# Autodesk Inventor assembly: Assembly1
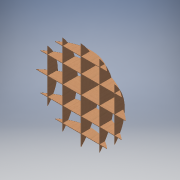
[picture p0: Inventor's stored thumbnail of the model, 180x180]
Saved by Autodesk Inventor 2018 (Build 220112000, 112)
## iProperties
Created: 2019-03
Part Number: Assembly1
Document SubType Name: Weldment
Designer: vpimentel
Weld Material: Welded Aluminum-6061
Author: vpimentel
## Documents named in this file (7)
- C:\FAB LAB\MAYRA\MOSTRADOR ESFERICO\Assembly1.iam
- C:\FAB LAB\MAYRA\MOSTRADOR ESFERICO\central_down.ipt
- C:\FAB LAB\MAYRA\MOSTRADOR ESFERICO\central_up.ipt
- C:\FAB LAB\MAYRA\MOSTRADOR ESFERICO\LATERAL_DOWN.ipt
- C:\FAB LAB\MAYRA\MOSTRADOR ESFERICO\lateral1_down.ipt
- C:\FAB LAB\MAYRA\MOSTRADOR ESFERICO\lateral2_up.ipt
- C:\FAB LAB\MAYRA\MOSTRADOR ESFERICO\lateral_small.ipt
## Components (11 placed, 6 different names)
1. central_down:1 — Mate:1, Mate:2, Mate:3, Flush:1, Flush:2, Mate:4, Mate:5, Flush:6, Mate:9, Mate:10, Mate:11, Mate:12
2. central_up:1 — Mate:1, Mate:2, Mate:3, Flush:4, Flush:7
3. LATERAL_DOWN:1 — Flush:1
4. lateral1_down:1 — Flush:2, Flush:3, Flush:10
5. lateral1_down:2 — Flush:3, Mate:4, Mate:5, Mate:6, Mate:7, Mate:8
6. lateral2_up:1 — Flush:4, Flush:5, Flush:9
7. lateral2_up:2 — Flush:5, Mate:6, Flush:6, Flush:8
8. lateral_small:1 — Flush:7
9. lateral_small:2 — Mate:9, Flush:9, Mate:10
10. lateral_small:3 — Flush:8, Mate:7, Mate:8
11. lateral_small:4 — Mate:11, Flush:10, Mate:12
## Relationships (22: Mate 12, Flush 10)
- Mate:1: central_down:1 ↔ central_up:1
- Mate:2: central_down:1 ↔ central_up:1
- Mate:3: central_down:1 ↔ central_up:1
- Flush:1: central_down:1 ↔ LATERAL_DOWN:1
- Flush:2: central_down:1 ↔ lateral1_down:1
- Flush:3: lateral1_down:1 ↔ lateral1_down:2
- Mate:4: central_down:1 ↔ lateral1_down:2
- Mate:5: central_down:1 ↔ lateral1_down:2
- Flush:4: central_up:1 ↔ lateral2_up:1
- Flush:5: lateral2_up:1 ↔ lateral2_up:2
- Mate:6: lateral1_down:2 ↔ lateral2_up:2
- Flush:6: central_down:1 ↔ lateral2_up:2
- Flush:7: central_up:1 ↔ lateral_small:1
- Flush:8: lateral2_up:2 ↔ lateral_small:3
- Mate:7: lateral1_down:2 ↔ lateral_small:3
- Mate:8: lateral1_down:2 ↔ lateral_small:3
- Mate:9: central_down:1 ↔ lateral_small:2
- Flush:9: lateral2_up:1 ↔ lateral_small:2
- Mate:10: central_down:1 ↔ lateral_small:2
- Mate:11: central_down:1 ↔ lateral_small:4
- Flush:10: lateral1_down:1 ↔ lateral_small:4
- Mate:12: central_down:1 ↔ lateral_small:4
